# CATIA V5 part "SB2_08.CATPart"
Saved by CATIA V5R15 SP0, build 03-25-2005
Part number: SB2_08
Material "Fire Red": density 7860 kg/m3, Young's modulus 2e+11 Pa, Poisson ratio 0.266
Bounding box of the stored display mesh (mm): x 0 to 158, y 0 to 632, z 0 to 49.2
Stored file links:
  E:\#01 CATIA Lecture Materials\#06 DMU\#11 DMU Page01 KIN EX11\SB2_08.CATPart
  C:\Program Files\Dassault Systemes\B20\win_b64\startup\materials\Catalog.CATMaterial
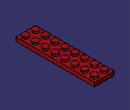
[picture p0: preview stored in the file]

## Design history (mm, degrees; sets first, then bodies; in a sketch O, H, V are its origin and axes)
Body1 (main body), material "Fire Red"
  Sketch1 on xy-plane, origin (0, 0, 0), H (1, 0, 0), V (0, 1, 0)
    circle A1 centre (39.5, 39.5) radius 24.5
    point P1 (39.5, 39.5)
    radius A1 = 24.5
    distance P1 H = 39.5
    distance P1 V = 39.5
  Pad1: profile Sketch1, direction (0, 0, 1), length 49.2
  Sketch2 on xy-plane, origin (0, 0, 0), H (1, 0, 0), V (0, 1, 0)
    point P1 (0, 632)
    line L1 (0, 632) -> (158, 632)
    line L2 (158, 632) -> (158, 0)
    line L3 (158, 0) -> (0, 0)
    line L4 (0, 0) -> (0, 632)
    point P3 (158, 0)
    distance L2 L4 = 158
    distance L1 L3 = 632 {= RectPattern2.Nb1  * 79mm}
    coincidence: P1 V, P3 H
    horizontal: L1 H, L3 H
    vertical: L2 V, L4 V
  Pad2: profile Sketch2, direction (0, 0, 1), length 32
  RectPattern1: of Pad1, direction 1 instances 2, spacing 79, along edge [face of Pad2 from Sketch2.L3 | end face of Pad2]
  RectPattern2: of RectPattern1, direction 1 instances 8, spacing 79, along edge [face of Pad2 from Sketch2.L2 | end face of Pad2]
  Shell1: ExtOffset 0, Face face of Pad2, IntOffset 15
